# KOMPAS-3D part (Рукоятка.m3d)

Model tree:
1. Эскиз:1
2. Операция выдавливания:1
     Расстояние 1 = 125; Расстояние 2 = 125
3. Эскиз:2
4. Операция выдавливания:2
     Расстояние 1 = 15; Расстояние 2 = 125
5. Условное изображение резьбы:1
     Длина резьбы = 15; Шаг резьбы = 1; Номинальный диаметр резьбы = 10
6. Фаска:1
     Угол = 45; Длина 1 = 1; Длина 2 = 1
7. Зеркальный массив:1  (with: Операция выдавливания:2)  (labels: Экземпляр ( 1 ); Экземпляр ( 2 ))
8. Условное изображение резьбы:2
     Длина резьбы = 15; Шаг резьбы = 1; Номинальный диаметр резьбы = 10
9. Фаска:2
     Угол = 45; Длина 1 = 1; Длина 2 = 1
10. Эскиз:3
11. Эскиз:4
12. Смещенная плоскость:1
     Расстояние = 1
13. Эскиз:5
14. Плоскость через ребро и грань:1
15. Ось конической поверхности:1
16. Эскиз:6
17. Вырезать элемент вращения:1
     Угол 1 = 360
18. Эскиз:7
19. Операция вращения:1
     Угол 1 = 360
20. Проточка наружная M10x0,5 Н ГОСТ 10549-80
21. Эскиз:8
22. Эскиз:9
23. Смещенная плоскость:2
     Расстояние = 1
24. Эскиз:10
25. Плоскость через ребро и грань:2
26. Ось конической поверхности:2
27. Эскиз:11
28. Вырезать элемент вращения:2
     Угол 1 = 360
29. Эскиз:12
30. Операция вращения:2
     Угол 1 = 360
31. Проточка наружная M10x0,5 Н ГОСТ 10549-80 (1)  (labels: C:\Program Files (x86)\ASCON\KOMPAS-3D V12\Sys\vertical.lat; D1; R1; Edge1)

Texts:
  Экземпляр ( 1 )
  Экземпляр ( 2 )
  Edge1
  Edge2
